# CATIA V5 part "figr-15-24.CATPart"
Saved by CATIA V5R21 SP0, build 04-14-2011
Part number: Part1
Bounding box of the stored display mesh (mm): x -50 to 50, y -25 to 25, z -24 to 1
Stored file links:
  D:\CATIA V5R21 E-RESOURCES\CATIA-V5R21\catia-v5r21-prt\c15-catia-v5r20-prt\c15-catia-v5r21-figr-15-24.CATPart
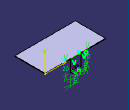
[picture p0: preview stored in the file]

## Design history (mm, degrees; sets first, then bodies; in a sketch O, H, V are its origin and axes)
SheetMetalParameters1: Thickness 1, BendRadius 2, KFactor 0.400515 {= log(min(100,max(20*SheetMetalParameters1.BendRadius,SheetMetalParameters1.Thickness)/SheetMetalParameters1.Thickness))/log(100)/2}, ReliefRadialLength 1, ReliefAxialLength 2, MinimumBendRadius 0
Body1 (main body)
  Sketch1 on xy-plane, origin (0, 0, 0), H (1, 0, 0), V (0, 1, 0)
    line L1 (-50, 25) -> (50, 25)
    line L2 (50, 25) -> (50, -25)
    line L3 (50, -25) -> (-50, -25)
    line L4 (-50, -25) -> (-50, 25)
    length L1 = 100
    distance V L2 = 50
    length L2 = 50
    distance H L3 = 25
    horizontal: L1 H, L3 H
    vertical: L2 V, L4 V
  Wall1: Thickness 1, Profile Sketch1
  Sketch2 on face of Wall1, origin (50, 25, 0), H (-1, 0, 0), V (0, 0, 1)
    line L1 (42.3549, 1) -> (42.3549, -19)
    point P2 (42.3549, -19)
    line L2 (42.3549, -19) -> (47.3549, -24)
    point P3 (47.3549, -24)
    line L3 (47.3549, -24) -> (54.3549, -24)
    point P4 (54.3549, -24)
    line L4 (54.3549, -24) -> (59.3549, -19)
    point P5 (59.3549, -19)
    line L5 (59.3549, -19) -> (59.3549, 1)
    line L6 (59.3549, 1) -> (42.3549, 1)
    reference projected line E1 (100, 1) -> (0, 1) from edge [face of Wall1 | face of Wall1]
    ellipse A1 centre (50.1164, -15.2153) semi-axes 5.0583, 2.1402 rotation 0
    length L5 = 20
    length L1 = 20
    length L3 = 7
    distance P4 L5 = 5
    distance P2 P3 H = 5
    distance L3 P5 = 5
    vertical: L1 V, L5 V
    horizontal: L3 H, L6 H
    coincidence: L6 E1
    parallelism: A1 L3
  d_NewWallOnEdge1: NewWallOnEdge_Edge edge [face of Wall1 | face of Wall1], NewWallOnEdge_WallProfile Sketch2, NewWallOnEdge_Length 100, NewWallOnEdge_HeightLimitOffset 0, NewWallOnEdge_WidthOffset1 0, NewWallOnEdge_WidthOffset2 0, NewWallOnEdge_Angle 0, NewWallOnEdge_BendRadiusValue 2 {= SheetMetalParameters1.BendRadius}, NewWallOnEdge_BendTable SheetMetalParameters1, KFacteur 0.400515 {= log(min(100,max(20*d_NewWallOnEdge1.Radius,SheetMetalParameters1.Thickness)/SheetMetalParameters1.Thickness))/log(100)/2}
